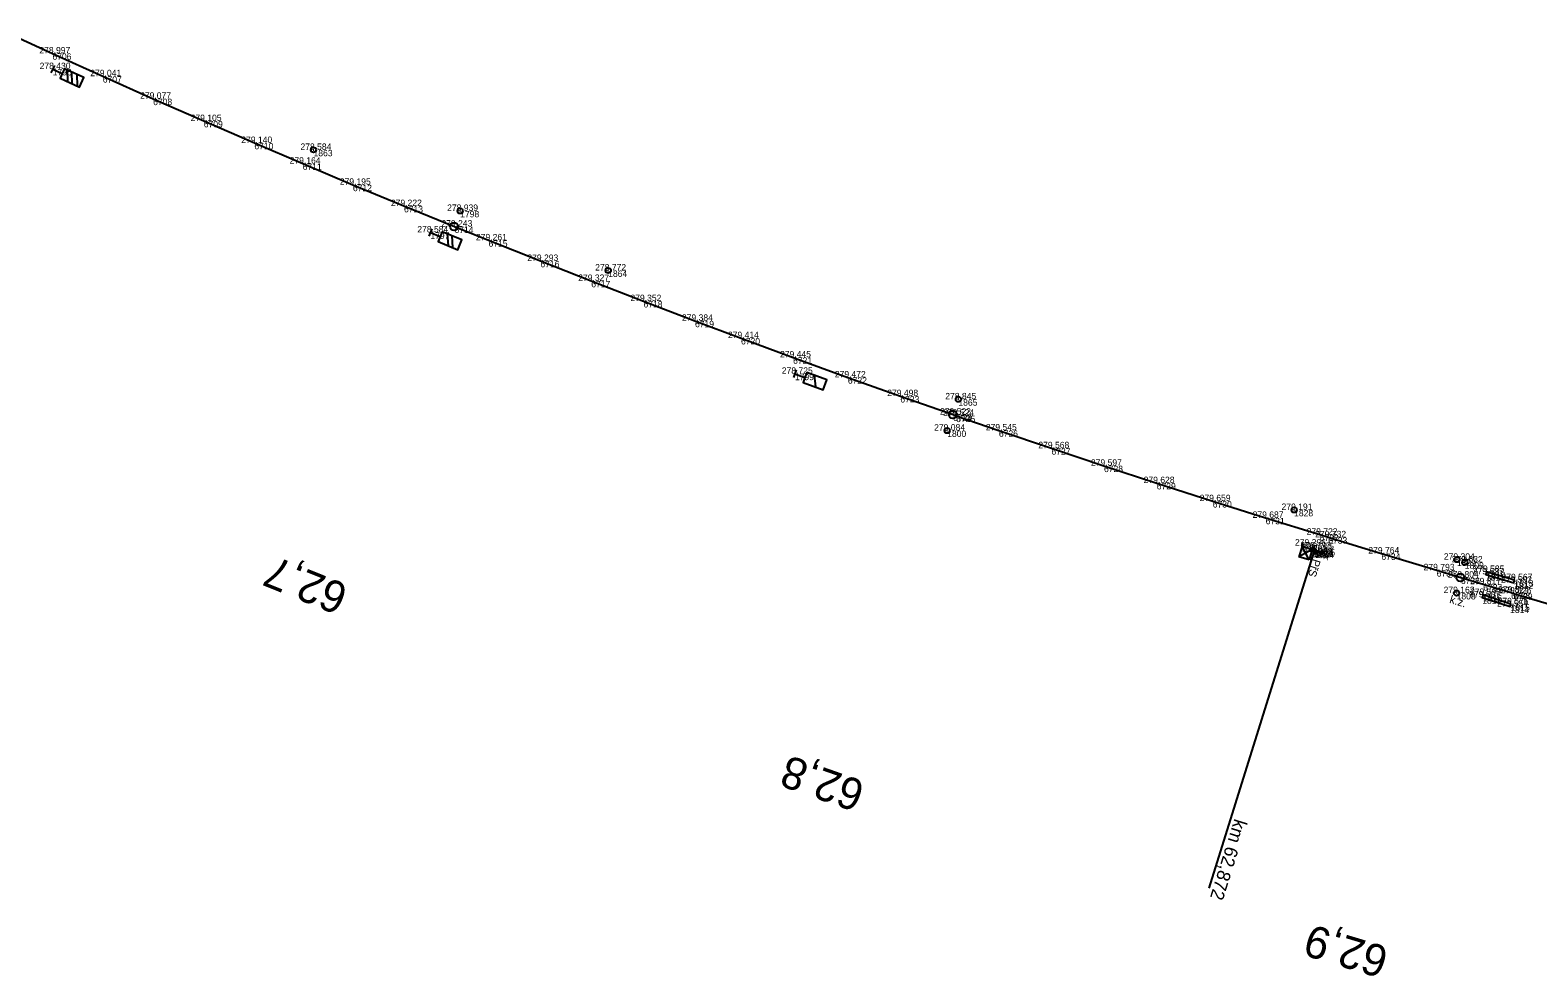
# Model space of a CAD drawing. Extents: x -613968 to -612840, y -1056667 to -1056202.
# Drawn here: x -613690.5 to -613407.7, y -1056518.2 to -1056340.5 of the extents above; entities that cross this region are included whole.
import ezdxf

# ---------------------------------------------------------------- set-up
doc = ezdxf.new("R2010")
doc.units = 0
for name, color, linetype in [('Rozpiska_pole_2', 7, 'Continuous'), ('Rozpiska_pole_5', 7, 'Continuous'), ('Rozpiska_pole_7', 7, 'Continuous'), ('Vrstva 1', 7, 'Continuous'), ('Vrstva 19', 7, 'Continuous'), ('Vrstva 25', 7, 'Continuous'), ('Vrstva 49', 7, 'Continuous'), ('Vrstva 50', 7, 'Continuous'), ('Vrstva 60', 7, 'Continuous'), ('Vrstva 61', 7, 'Continuous')]:
    doc.layers.add(name, color=color, linetype=linetype)

msp = doc.modelspace()

# ---------------------------------------------------------------- linework, layer by layer
at = {"layer": 'Rozpiska_pole_2'}
msp.add_lwpolyline([(-613449.32, -1056437.9), (-613449.81, -1056437.74), (-613449.97, -1056438.21), (-613449.49, -1056438.36)], close=True, dxfattribs=at)
at = {"layer": 'Rozpiska_pole_5'}
for p, q in [((-613449.53, -1056437.69), (-613449.82, -1056438.65)), ((-613449.67, -1056438.17), (-613469.43, -1056501.51)), ((-613447.78, -1056438.75), (-613449.67, -1056438.17))]:
    msp.add_line(p, q, dxfattribs=at)
at = {"layer": 'Rozpiska_pole_7'}
for p, q in [((-613686.01, -1056347.1), (-613686.64, -1056348.46)), ((-613683.63, -1056347.92), (-613683.56, -1056350.15)), ((-613682.65, -1056350.57), (-613682.73, -1056348.33)), ((-613681.82, -1056348.75), (-613681.75, -1056350.99)), ((-613609.92, -1056374.38), (-613609.83, -1056374.42)), ((-613615.18, -1056377.76), (-613615.76, -1056379.14)), ((-613612.32, -1056378.68), (-613612.16, -1056380.91)), ((-613611.24, -1056381.29), (-613611.39, -1056379.06)), ((-613546.83, -1056404.26), (-613547.35, -1056405.67)), ((-613543.46, -1056405.23), (-613543.2, -1056407.45)), ((-613518.57, -1056415.61), (-613518.48, -1056415.64)), ((-613451.94, -1056437.39), (-613452.53, -1056439.3)), ((-613452.03, -1056436.84), (-613451.55, -1056436.98)), ((-613451.94, -1056437.39), (-613451.79, -1056436.91)), ((-613450.03, -1056437.98), (-613451.94, -1056437.39)), ((-613450.62, -1056439.89), (-613451.94, -1056437.39)), ((-613450.12, -1056437.43), (-613449.64, -1056437.58)), ((-613450.03, -1056437.98), (-613449.88, -1056437.5)), ((-613450.03, -1056437.98), (-613452.53, -1056439.3)), ((-613450.62, -1056439.89), (-613452.53, -1056439.3)), ((-613450.03, -1056437.98), (-613450.62, -1056439.89)), ((-613421.46, -1056440.34), (-613421.37, -1056440.37))]:
    msp.add_line(p, q, dxfattribs=at)
for points in [[(-613686.32, -1056347.78), (-613684.51, -1056348.62), (-613684.92, -1056349.52), (-613681.29, -1056351.2), (-613680.46, -1056349.38), (-613684.09, -1056347.71), (-613684.51, -1056348.62)], [(-613615.47, -1056378.45), (-613613.62, -1056379.22), (-613614.01, -1056380.14), (-613610.31, -1056381.68), (-613609.55, -1056379.83), (-613613.24, -1056378.3), (-613613.62, -1056379.22)], [(-613547.09, -1056404.97), (-613545.21, -1056405.65), (-613545.55, -1056406.59), (-613541.79, -1056407.96), (-613541.11, -1056406.08), (-613544.87, -1056404.71), (-613545.21, -1056405.65)]]:
    msp.add_lwpolyline(points, dxfattribs=at)
for centre, radius in [((-613609.88, -1056374.4), 0.5), ((-613611.03, -1056377.31), 0.75), ((-613517.49, -1056412.61), 0.75), ((-613518.52, -1056415.63), 0.5), ((-613421.42, -1056440.36), 0.5), ((-613422.26, -1056443.18), 0.75)]:
    msp.add_circle(centre, radius, dxfattribs=at)
at = {"layer": 'Vrstva 1'}
msp.add_lwpolyline([(-613695.85, -1056340.48), (-613686.37, -1056344.84), (-613676.92, -1056349.12), (-613667.47, -1056353.35), (-613657.98, -1056357.53), (-613648.49, -1056361.65), (-613639.42, -1056365.53), (-613630, -1056369.5), (-613620.42, -1056373.48), (-613610.95, -1056377.34), (-613604.56, -1056379.92), (-613594.83, -1056383.79), (-613585.29, -1056387.54), (-613575.49, -1056391.33), (-613565.83, -1056395.03), (-613557.2, -1056398.27), (-613547.43, -1056401.9), (-613537.15, -1056405.64), (-613527.31, -1056409.16), (-613517.43, -1056412.63), (-613516.83, -1056412.84), (-613508.82, -1056415.6), (-613498.96, -1056418.94), (-613489.11, -1056422.23), (-613479.21, -1056425.48), (-613468.7, -1056428.87), (-613458.78, -1056432.01), (-613448.64, -1056435.16), (-613447.04, -1056435.65), (-613437.07, -1056438.7), (-613426.7, -1056441.84), (-613422.16, -1056443.21), (-613417.97, -1056444.47), (-613412.73, -1056446.05), (-613412.28, -1056446.19), (-613404.49, -1056448.54)], dxfattribs=at)
at = {"layer": 'Vrstva 19'}
for points in [[(-613417.35, -1056442.15), (-613417.49, -1056442.61), (-613412.2, -1056444.19), (-613412.09, -1056443.71)], [(-613417.99, -1056446.47), (-613418.16, -1056446.93), (-613412.92, -1056448.66), (-613412.82, -1056448.22)]]:
    msp.add_lwpolyline(points, close=True, dxfattribs=at)
at = {"layer": 'Vrstva 25'}
msp.add_line((-613423, -1056446.11), (-613422.91, -1056446.14), dxfattribs=at)
msp.add_circle((-613422.96, -1056446.12), 0.5, dxfattribs=at)
at = {"layer": 'Vrstva 49'}
for p, q in [((-613449.87, -1056438.2), (-613449.43, -1056437.97)), ((-613449.76, -1056437.86), (-613449.53, -1056438.31))]:
    msp.add_line(p, q, dxfattribs=at)
at = {"layer": 'Vrstva 50'}
for p, q in [((-613637.44, -1056362.93), (-613637.35, -1056362.97)), ((-613582.16, -1056385.57), (-613582.07, -1056385.61)), ((-613516.47, -1056409.74), (-613516.37, -1056409.77)), ((-613453.49, -1056430.5), (-613453.39, -1056430.53)), ((-613422.95, -1056439.84), (-613422.85, -1056439.86))]:
    msp.add_line(p, q, dxfattribs=at)
for centre in [(-613637.39, -1056362.95), (-613582.11, -1056385.59), (-613516.42, -1056409.76), (-613453.44, -1056430.52), (-613422.9, -1056439.85)]:
    msp.add_circle(centre, 0.5, dxfattribs=at)
at = {"layer": 'Vrstva 60'}
for p, q in [((-613686.37, -1056344.84), (-613686.37, -1056344.84)), ((-613686.32, -1056347.78), (-613686.32, -1056347.78)), ((-613676.92, -1056349.12), (-613676.92, -1056349.12)), ((-613667.47, -1056353.35), (-613667.47, -1056353.35)), ((-613657.98, -1056357.53), (-613657.98, -1056357.53)), ((-613648.49, -1056361.65), (-613648.49, -1056361.65)), ((-613637.39, -1056362.95), (-613637.39, -1056362.95)), ((-613639.42, -1056365.53), (-613639.42, -1056365.53)), ((-613630, -1056369.5), (-613630, -1056369.5)), ((-613620.42, -1056373.48), (-613620.42, -1056373.48)), ((-613609.88, -1056374.4), (-613609.88, -1056374.4)), ((-613610.95, -1056377.34), (-613610.95, -1056377.34)), ((-613615.47, -1056378.45), (-613615.47, -1056378.45)), ((-613604.56, -1056379.92), (-613604.56, -1056379.92)), ((-613594.83, -1056383.79), (-613594.83, -1056383.79)), ((-613582.11, -1056385.59), (-613582.11, -1056385.59)), ((-613585.29, -1056387.54), (-613585.29, -1056387.54)), ((-613575.49, -1056391.33), (-613575.49, -1056391.33)), ((-613565.83, -1056395.03), (-613565.83, -1056395.03)), ((-613557.2, -1056398.27), (-613557.2, -1056398.27)), ((-613547.43, -1056401.9), (-613547.43, -1056401.9)), ((-613547.09, -1056404.97), (-613547.09, -1056404.97)), ((-613537.15, -1056405.64), (-613537.15, -1056405.64)), ((-613527.31, -1056409.16), (-613527.31, -1056409.16)), ((-613516.42, -1056409.76), (-613516.42, -1056409.76)), ((-613517.43, -1056412.63), (-613517.43, -1056412.63)), ((-613516.83, -1056412.84), (-613516.83, -1056412.84)), ((-613518.52, -1056415.63), (-613518.52, -1056415.63)), ((-613508.82, -1056415.6), (-613508.82, -1056415.6)), ((-613498.96, -1056418.94), (-613498.96, -1056418.94)), ((-613489.11, -1056422.23), (-613489.11, -1056422.23)), ((-613479.21, -1056425.48), (-613479.21, -1056425.48)), ((-613468.7, -1056428.87), (-613468.7, -1056428.87)), ((-613458.78, -1056432.01), (-613458.78, -1056432.01)), ((-613453.44, -1056430.52), (-613453.44, -1056430.52)), ((-613450.83, -1056437.21), (-613450.83, -1056437.21)), ((-613449.81, -1056437.74), (-613449.81, -1056437.74)), ((-613448.64, -1056435.16), (-613448.64, -1056435.16)), ((-613447.04, -1056435.65), (-613447.04, -1056435.65)), ((-613449.97, -1056438.21), (-613449.97, -1056438.21)), ((-613449.67, -1056438.17), (-613449.67, -1056438.17)), ((-613449.65, -1056438.08), (-613449.65, -1056438.08)), ((-613449.49, -1056438.36), (-613449.49, -1056438.36)), ((-613449.32, -1056437.9), (-613449.32, -1056437.9)), ((-613437.07, -1056438.7), (-613437.07, -1056438.7)), ((-613422.9, -1056439.85), (-613422.9, -1056439.85)), ((-613421.42, -1056440.36), (-613421.42, -1056440.36)), ((-613426.7, -1056441.84), (-613426.7, -1056441.84)), ((-613422.16, -1056443.21), (-613422.16, -1056443.21)), ((-613417.49, -1056442.61), (-613417.49, -1056442.61)), ((-613417.35, -1056442.15), (-613417.35, -1056442.15)), ((-613422.96, -1056446.12), (-613422.96, -1056446.12)), ((-613417.97, -1056444.47), (-613417.97, -1056444.47)), ((-613412.73, -1056446.05), (-613412.73, -1056446.05)), ((-613412.28, -1056446.19), (-613412.28, -1056446.19)), ((-613412.2, -1056444.19), (-613412.2, -1056444.19)), ((-613412.09, -1056443.71), (-613412.09, -1056443.71)), ((-613418.16, -1056446.93), (-613418.16, -1056446.93)), ((-613417.99, -1056446.47), (-613417.99, -1056446.47)), ((-613412.92, -1056448.66), (-613412.92, -1056448.66)), ((-613412.82, -1056448.22), (-613412.82, -1056448.22))]:
    msp.add_line(p, q, dxfattribs=at)

# ---------------------------------------------------------------- texts
at = {"layer": 'Rozpiska_pole_5'}
for s, height, rotation, p in [('PřS', 1.5, 252.7571, (-613449.86, -1056439.63)), ('  A A ', 1, 342.7571, (-613449.97, -1056439.12)), ('km 62,872', 2.5, 252.7571, (-613464.61, -1056488.35))]:
    msp.add_text(s, height=height, rotation=rotation, dxfattribs=at).set_placement(p)
at = {"layer": 'Rozpiska_pole_7'}
for s, rotation, p in [('62,7', 158.0378, (-613630.53, -1056444.79)), ('62,8', 160.6607, (-613533.61, -1056481.64)), ('62,9', 163.1842, (-613435.37, -1056512.74))]:
    msp.add_text(s, height=6, rotation=rotation, dxfattribs=at).set_placement(p)
at = {"layer": 'Vrstva 25'}
msp.add_text('k.z.', height=1.5, rotation=343.1929, dxfattribs=at).set_placement((-613424.4, -1056447.94))
at = {"layer": 'Vrstva 60'}
for s, p in [('6706', (-613686.37, -1056346.04)), ('1796', (-613686.32, -1056348.98)), ('6707', (-613676.92, -1056350.32)), ('6708', (-613667.47, -1056354.55)), ('6709', (-613657.98, -1056358.73)), ('6710', (-613648.49, -1056362.85)), ('1863', (-613637.39, -1056364.15)), ('6711', (-613639.42, -1056366.73)), ('6712', (-613630, -1056370.7)), ('6713', (-613620.42, -1056374.68)), ('1798', (-613609.88, -1056375.6)), ('6714', (-613610.95, -1056378.54)), ('1797', (-613615.47, -1056379.65)), ('6715', (-613604.56, -1056381.12)), ('6716', (-613594.83, -1056384.99)), ('1864', (-613582.11, -1056386.79)), ('6717', (-613585.29, -1056388.74)), ('6718', (-613575.49, -1056392.53)), ('6719', (-613565.83, -1056396.23)), ('6720', (-613557.2, -1056399.47)), ('6721', (-613547.43, -1056403.1)), ('1799', (-613547.09, -1056406.17)), ('6722', (-613537.15, -1056406.84)), ('6723', (-613527.31, -1056410.36)), ('1865', (-613516.42, -1056410.96)), ('6724', (-613517.43, -1056413.83)), ('6725', (-613516.83, -1056414.04)), ('1800', (-613518.52, -1056416.83)), ('6726', (-613508.82, -1056416.8)), ('6727', (-613498.96, -1056420.14)), ('6728', (-613489.11, -1056423.43)), ('6729', (-613479.21, -1056426.68)), ('6730', (-613468.7, -1056430.07)), ('6731', (-613458.78, -1056433.21)), ('1828', (-613453.44, -1056431.72)), ('1801', (-613450.83, -1056438.41)), ('1802', (-613449.81, -1056438.94)), ('6732', (-613448.64, -1056436.36)), ('6733', (-613447.04, -1056436.85)), ('1803', (-613449.97, -1056439.41)), ('1806', (-613449.67, -1056439.37)), ('1807', (-613449.65, -1056439.28)), ('1804', (-613449.49, -1056439.56)), ('1805', (-613449.32, -1056439.1)), ('6734', (-613437.07, -1056439.9)), ('1829', (-613422.9, -1056441.05)), ('1809', (-613421.42, -1056441.56)), ('6735', (-613426.7, -1056443.04)), ('6736', (-613422.16, -1056444.41)), ('1811', (-613417.49, -1056443.81)), ('1810', (-613417.35, -1056443.35)), ('1808', (-613422.96, -1056447.32)), ('6737', (-613417.97, -1056445.67)), ('6738', (-613412.73, -1056447.25)), ('6739', (-613412.28, -1056447.39)), ('1812', (-613412.2, -1056445.39)), ('1813', (-613412.09, -1056444.91)), ('1817', (-613418.16, -1056448.13)), ('1816', (-613417.99, -1056447.67)), ('1814', (-613412.92, -1056449.86)), ('1815', (-613412.82, -1056449.42))]:
    msp.add_text(s, height=1.2, dxfattribs=at).set_placement(p)
at = {"layer": 'Vrstva 61'}
for s, p in [('278.997', (-613688.82, -1056344.84)), ('278.430', (-613688.77, -1056347.78)), ('279.041', (-613679.27, -1056349.12)), ('279.077', (-613669.92, -1056353.35)), ('279.105', (-613660.44, -1056357.53)), ('279.140', (-613650.94, -1056361.65)), ('278.584', (-613639.84, -1056362.95)), ('279.164', (-613641.87, -1056365.53)), ('279.195', (-613632.46, -1056369.5)), ('279.222', (-613622.87, -1056373.48)), ('278.939', (-613612.33, -1056374.4)), ('278.584', (-613617.92, -1056378.45)), ('279.243', (-613613.4, -1056377.34)), ('279.261', (-613606.92, -1056379.92)), ('279.293', (-613597.28, -1056383.79)), ('279.327', (-613587.74, -1056387.54)), ('278.772', (-613584.56, -1056385.59)), ('279.352', (-613577.94, -1056391.33)), ('279.384', (-613568.28, -1056395.03)), ('279.414', (-613559.65, -1056398.27)), ('279.445', (-613549.88, -1056401.9)), ('278.725', (-613549.55, -1056404.97)), ('279.472', (-613539.6, -1056405.64)), ('279.498', (-613529.77, -1056409.16)), ('278.845', (-613518.88, -1056409.76)), ('279.522', (-613519.87, -1056412.63)), ('279.524', (-613519.28, -1056412.84)), ('279.084', (-613520.97, -1056415.63)), ('279.545', (-613511.28, -1056415.6)), ('279.568', (-613501.42, -1056418.94)), ('279.597', (-613491.56, -1056422.23)), ('279.628', (-613481.67, -1056425.48)), ('279.659', (-613471.16, -1056428.87)), ('279.687', (-613461.23, -1056432.01)), ('279.191', (-613455.8, -1056430.52)), ('279.722', (-613451.09, -1056435.16)), ('279.732', (-613449.49, -1056435.65)), ('279.296', (-613453.28, -1056437.21)), ('279.101', (-613452.33, -1056438.21)), ('279.113', (-613452.26, -1056437.74)), ('279.110', (-613452.12, -1056438.17)), ('279.109', (-613452.1, -1056438.08)), ('279.107', (-613451.94, -1056438.36)), ('279.125', (-613451.77, -1056437.9)), ('279.764', (-613439.52, -1056438.7)), ('279.304', (-613425.35, -1056439.85)), ('279.632', (-613423.87, -1056440.36)), ('279.793', (-613429.15, -1056441.84)), ('279.804', (-613424.61, -1056443.21)), ('279.817', (-613420.43, -1056444.47)), ('279.627', (-613419.94, -1056442.61)), ('279.585', (-613419.8, -1056442.15)), ('279.592', (-613414.64, -1056444.19)), ('279.567', (-613414.54, -1056443.71)), ('279.162', (-613425.4, -1056446.12)), ('279.607', (-613420.61, -1056446.93)), ('279.590', (-613420.44, -1056446.47)), ('279.824', (-613415.18, -1056446.05)), ('279.825', (-613414.73, -1056446.19)), ('279.554', (-613415.37, -1056448.66)), ('279.576', (-613415.27, -1056448.22))]:
    msp.add_text(s, height=1.2, dxfattribs=at).set_placement(p)

doc.saveas('drawing.dxf')
